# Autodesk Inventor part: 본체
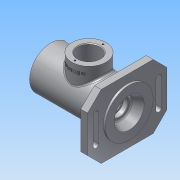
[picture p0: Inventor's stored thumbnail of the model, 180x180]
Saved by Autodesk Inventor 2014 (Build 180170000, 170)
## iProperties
Created: 2017-10
Part Number: 본체
Material: 알루미늄 6061
Document SubType Name: Modeling
Designer: user
Density: 2.71 g/cm^3
Appearance: 알루미늄 - 평지
Mass: 741.176 g
Surface Area: 654.64 cm^2
Volume: 273.497 cm^3
Author: user
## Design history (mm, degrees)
sketch "스케치1"
  geometry: C1 r 31 at (0, 0); 1 further point
  constraints: 1 centre point, 1 coincident
  dimensions: "d0" = 62 diameter of C1
extrude "돌출1" new body sketch "스케치1" distance "d1" = 102; taper "d2" = 0 deg
node "작업 평면1"
sketch "스케치3"
  geometry: L1 (31, 102)-(-31, 102) reference; C1 r 25 at (0, 46); 1 further point
  constraints: 1 centre point, 1 vertical alignment
  dimensions: "d4" = 50 diameter of C1; "d5" = 56 distance from line of L1 C1.centre
extrude "돌출2" join sketch "스케치3" stored distance "d6" = 102; taper "d7" = 0 deg
sketch "스케치4"
  geometry: L1 (-58, -47)-(58, -47); L2 (58, -47)-(58, 47); L3 (58, 47)-(-58, 47); L4 (-58, 47)-(-58, -47); L5 (-58, -47)-(58, 47); L6 (58, -47)-(-58, 47); C1 r 31 at (0, 0) reference
  constraints: 12 end point, 2 midpoint, 2 parallel, 1 horizontal, 1 perpendicular
  dimensions: "d8" = 116 distance of L2.end L3.end; "d9" = 94 distance of L1.end L2.end
extrude "돌출3" join sketch "스케치4" distance "d10" = 10; taper "d11" = 0 deg
sketch "스케치5"
  geometry: C1 r 35 at (0, 0); 1 further point
  constraints: 1 centre point, 1 coincident
  dimensions: "d12" = 70 diameter of C1
extrude "돌출4" join sketch "스케치5" distance "d13" = 3; taper "d14" = 0 deg
chamfer "모따기1" distance "d15" = 20; stored, may be unused: second distance "d16" = 2, angle "d17" = 45 deg
sketch "스케치6"
  geometry: C1 r 31 at (0, 0) reference; 1 further point
  constraints: 1 coincident
hole "구멍1" sketch "스케치6" at (0, 0) diameter "d18" = 40.376; stored, may be unused: countersink angle "d22" = 90 deg, drill point angle "d24" = 0 deg; dims "d19" = 9, "d20" = 4, "d21" = 2, "d23" = 9
sketch "스케치7"
  geometry: L1 (-20.188, 102)-(20.188, 102) reference; L2 (20.188, 93)-(-20.188, 93) reference; L3 (0, 93)-(24, 93); L4 (24, 93)-(24, 90); L5 (24, 90)-(0, 90); L6 (0, 90)-(0, 93); L7 (0, 90)-(20, 90); L8 (20, 90)-(20, 81); L9 (20, 81)-(0, 81); L10 (0, 81)-(0, 90); L11 (0, 81)-(17.5, 81); L12 (17.5, 81)-(17.5, 77.75); L13 (17.5, 77.75)-(0, 77.75); L14 (0, 77.75)-(0, 81); L15 (0, 77.75)-(18.5, 77.75); L16 (18.5, 77.75)-(18.5, 76); L17 (18.5, 76)-(0, 76); L18 (0, 76)-(0, 77.75); L19 (0, 76)-(17.5, 76); L20 (17.5, 76)-(17.5, 65); L21 (17.5, 65)-(0, 65); L22 (0, 65)-(0, 76); L23 (0, 65)-(26, 65); L24 (26, 65)-(26, 27); L25 (26, 27)-(0, 27); L26 (0, 27)-(0, 65); L27 (0, 27)-(17.5, 27); L28 (17.5, 27)-(17.5, 16); L29 (17.5, 16)-(0, 16); L30 (0, 16)-(0, 27); L31 (0, 16)-(16.5, 16); L32 (16.5, 16)-(16.5, 11); L33 (16.5, 11)-(0, 11); L34 (0, 11)-(0, 16); L35 (0, 11)-(10, 11); L36 (10, 11)-(10, 8.3); L37 (10, 8.3)-(0, 8.3); L38 (0, 8.3)-(0, 11); L39 (0, 8.3)-(12.5, 8.3); L40 (12.5, 8.3)-(12.5, 1.7); L41 (12.5, 1.7)-(0, 1.7); L42 (0, 1.7)-(0, 8.3); L43 (-35, -13)-(35, -13) reference; L44 (0, 1.7)-(0, -13); L45 (22, -13)-(0, -13); L46 (22, -13)-(16, 1); L47 (12.5, 1.7)-(12.904, 1); L48 (16, 1)-(0, 1); 1 further point
  constraints: 90 end point, 20 parallel, 11 perpendicular, 10 horizontal, 3 point on line, 2 midpoint, 1 collinear
  dimensions: "d25" = 48 diameter of L4 L6; "d26" = 40 diameter of L8 L10; "d27" = 35 diameter of L12 L14; "d28" = 37 diameter of L16 L18; "d29" = 35 diameter of L20 L22; "d31" = 35 diameter of L28 L30; "d32" = 52 diameter of L24 L26; "d33" = 33 diameter of L32 L34; "d34" = 20 diameter of L36 L38; "d35" = 25 diameter of L40 L42; "d36" = 22 distance of L44.end L45.start; "d37" = 32 diameter of L46.end L44; "d47" = 30 deg angle of L40 L47; "d48" = 0.7 vertical distance of L47.end L40.end; "d97" = 12 distance between parallel lines of L5 L1; "d98" = 21 distance between parallel lines of L11 L1; "d99" = 26 distance between parallel lines of L17 L1; "d100" = 1.75 distance of L15.end L16.end; "d102" = 38 distance of L23.end L24.end; "d103" = 11 distance of L27.end L28.end; "d104" = 5 distance of L31.end L32.end; "d105" = 14 distance between parallel lines of L43 L48; "d106" = 7.3 distance between parallel lines of L48 L39; "d108" = 11 distance of L19.end L20.end
revolve "회전1" sketch "스케치7" stored, may be unused: angle "d50" = 90 deg
sketch "스케치8"
  geometry: C1 r 25 at (0, 0) reference; C2 r 16 at (0, 0); 1 further point
  constraints: 1 centre point, 1 coincident
  dimensions: "d51" = 32 diameter of C2
extrude "돌출5" cut sketch "스케치8" distance "d52" = 40; taper "d53" = 0 deg
sketch "스케치9"
  geometry: L1 (-58, -27)-(-58, 27) reference; L2 (-50, 20)-(-50, -20); L3 (-42, 20)-(-42, -20); L4 (-81.2, 0)-(81.2, 0) reference; L5 (0, -65.8)-(0, 65.8) reference; L6 (42, 20)-(42, -20); L7 (50, 20)-(50, -20); C1 r 31 at (0, 0) reference; A1 r 4 centre (-46, 20) between (-42, 20) and (-50, 20); A2 r 4 centre (-46, -20) between (-50, -20) and (-42, -20); A3 r 4 centre (46, 20) between (50, 20) and (42, 20); A4 r 4 centre (46, -20) between (42, -20) and (50, -20)
  constraints: 10 end point, 10 point on circle, 8 symmetric about line, 4 centre point, 2 parallel, 2 point on line, 2 tangent, 3 other
  dimensions: "d54" = 8 diameter of A1; "d55" = 46 horizontal distance of C1.centre A1.centre; "d56" = 20 vertical distance of C1.centre A1.centre
extrude "돌출6" cut sketch "스케치9" distance "d57" = 40; taper "d58" = 0 deg
fillet "모깎기1" dims "d61" = 3
fillet "모깎기2" dims "d62" = 0.3
fillet "모깎기3" dims "d63" = 3
fillet "모깎기4" dims "d64" = 3
fillet "모깎기5" dims "d65" = 0.3
sketch "스케치11"
  geometry: C1 r 16 at (0, 0) reference; 2 further points
  constraints: 1 horizontal alignment
  dimensions: "d66" = 20.5 distance of C1.centre point (-20.5, 0)
hole "구멍2" sketch "스케치11" at (-20.5, 0) diameter "d67" = 2.459; stored, may be unused: countersink angle "d71" = 90 deg, drill point angle "d73" = 118 deg; dims "d68" = 6, "d69" = 4, "d70" = 2, "d72" = 8
sketch "스케치12"
  geometry: L1 (31, 102)-(-31, 102) reference; L2 (47, 62)-(47, 30) reference; 2 further points
  constraints: 1 other
  dimensions: "d77" = 56 distance from line of point (37, 46) L1; "d78" = 10 distance from line of L2 point (37, 46)
feature "엠보싱1" sketch "스케치12" dims "d1" = 102, "d2" = 0, "d79" = 0.5, "d80" = 0
chamfer "모따기2" distance "d81" = 1; stored, may be unused: second distance "d82" = 2, angle "d83" = 45 deg
fillet "모깎기6" dims "d84" = 3
chamfer "모따기3" distance "d92" = 1; stored, may be unused: second distance "d93" = 2, angle "d94" = 45 deg
node "솔리드1"
pattern_circular "원형 패턴1" dims angle "d75" = 360 deg
node "투영된 루프1"
other parameters: "d3" = 47
